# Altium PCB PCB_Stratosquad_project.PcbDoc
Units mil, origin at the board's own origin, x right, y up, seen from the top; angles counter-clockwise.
Board outline 4505 x 4505 mil, 2 copper layers (Top Layer, Bottom Layer); 27 components, 22 nets, 130 pads, 25 vias.
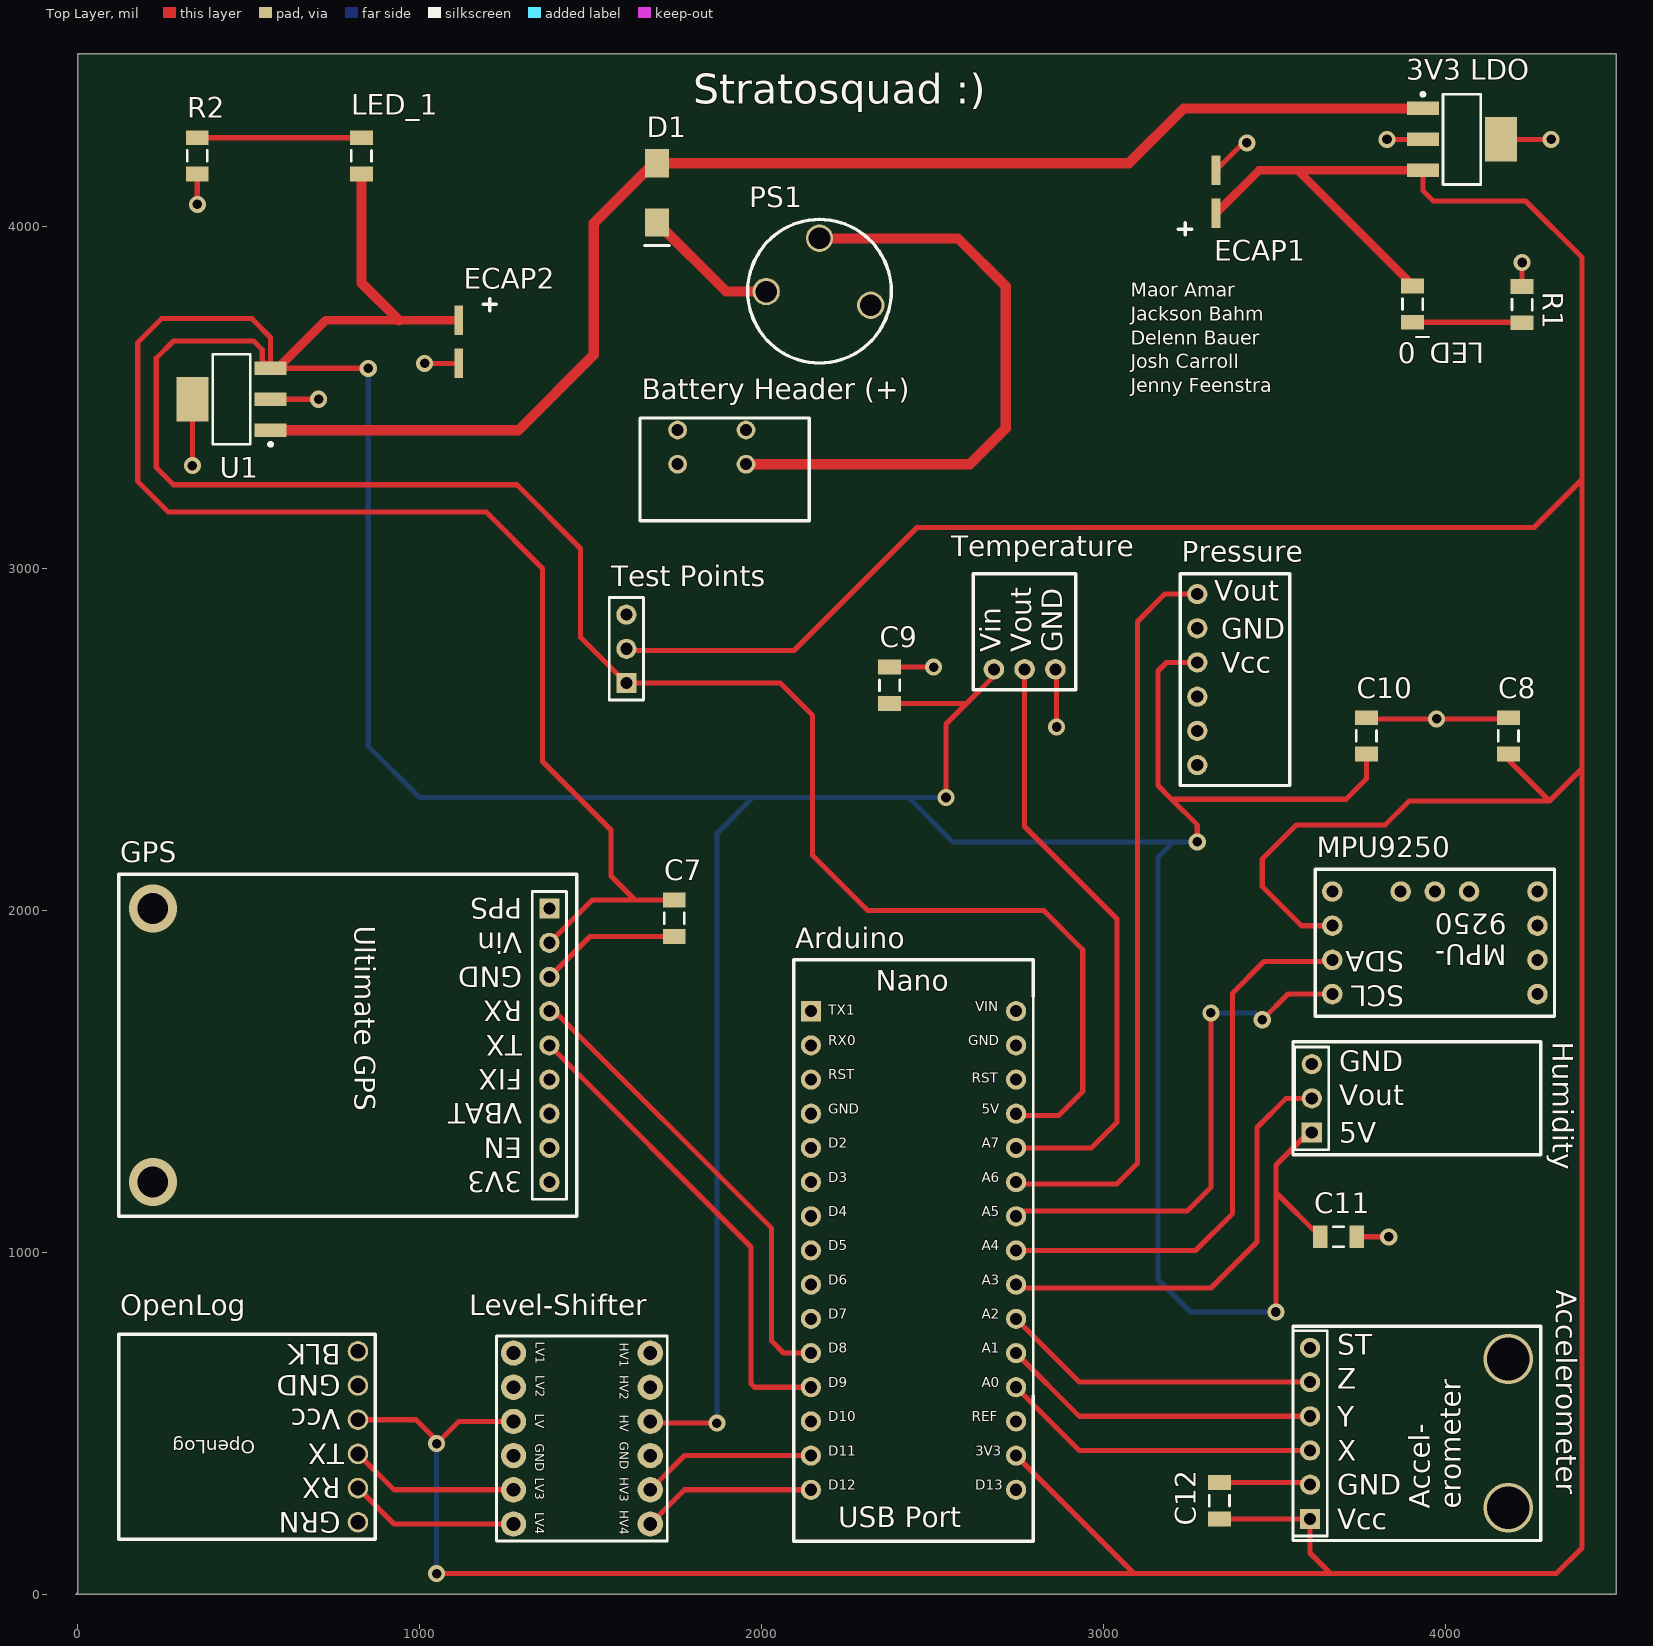
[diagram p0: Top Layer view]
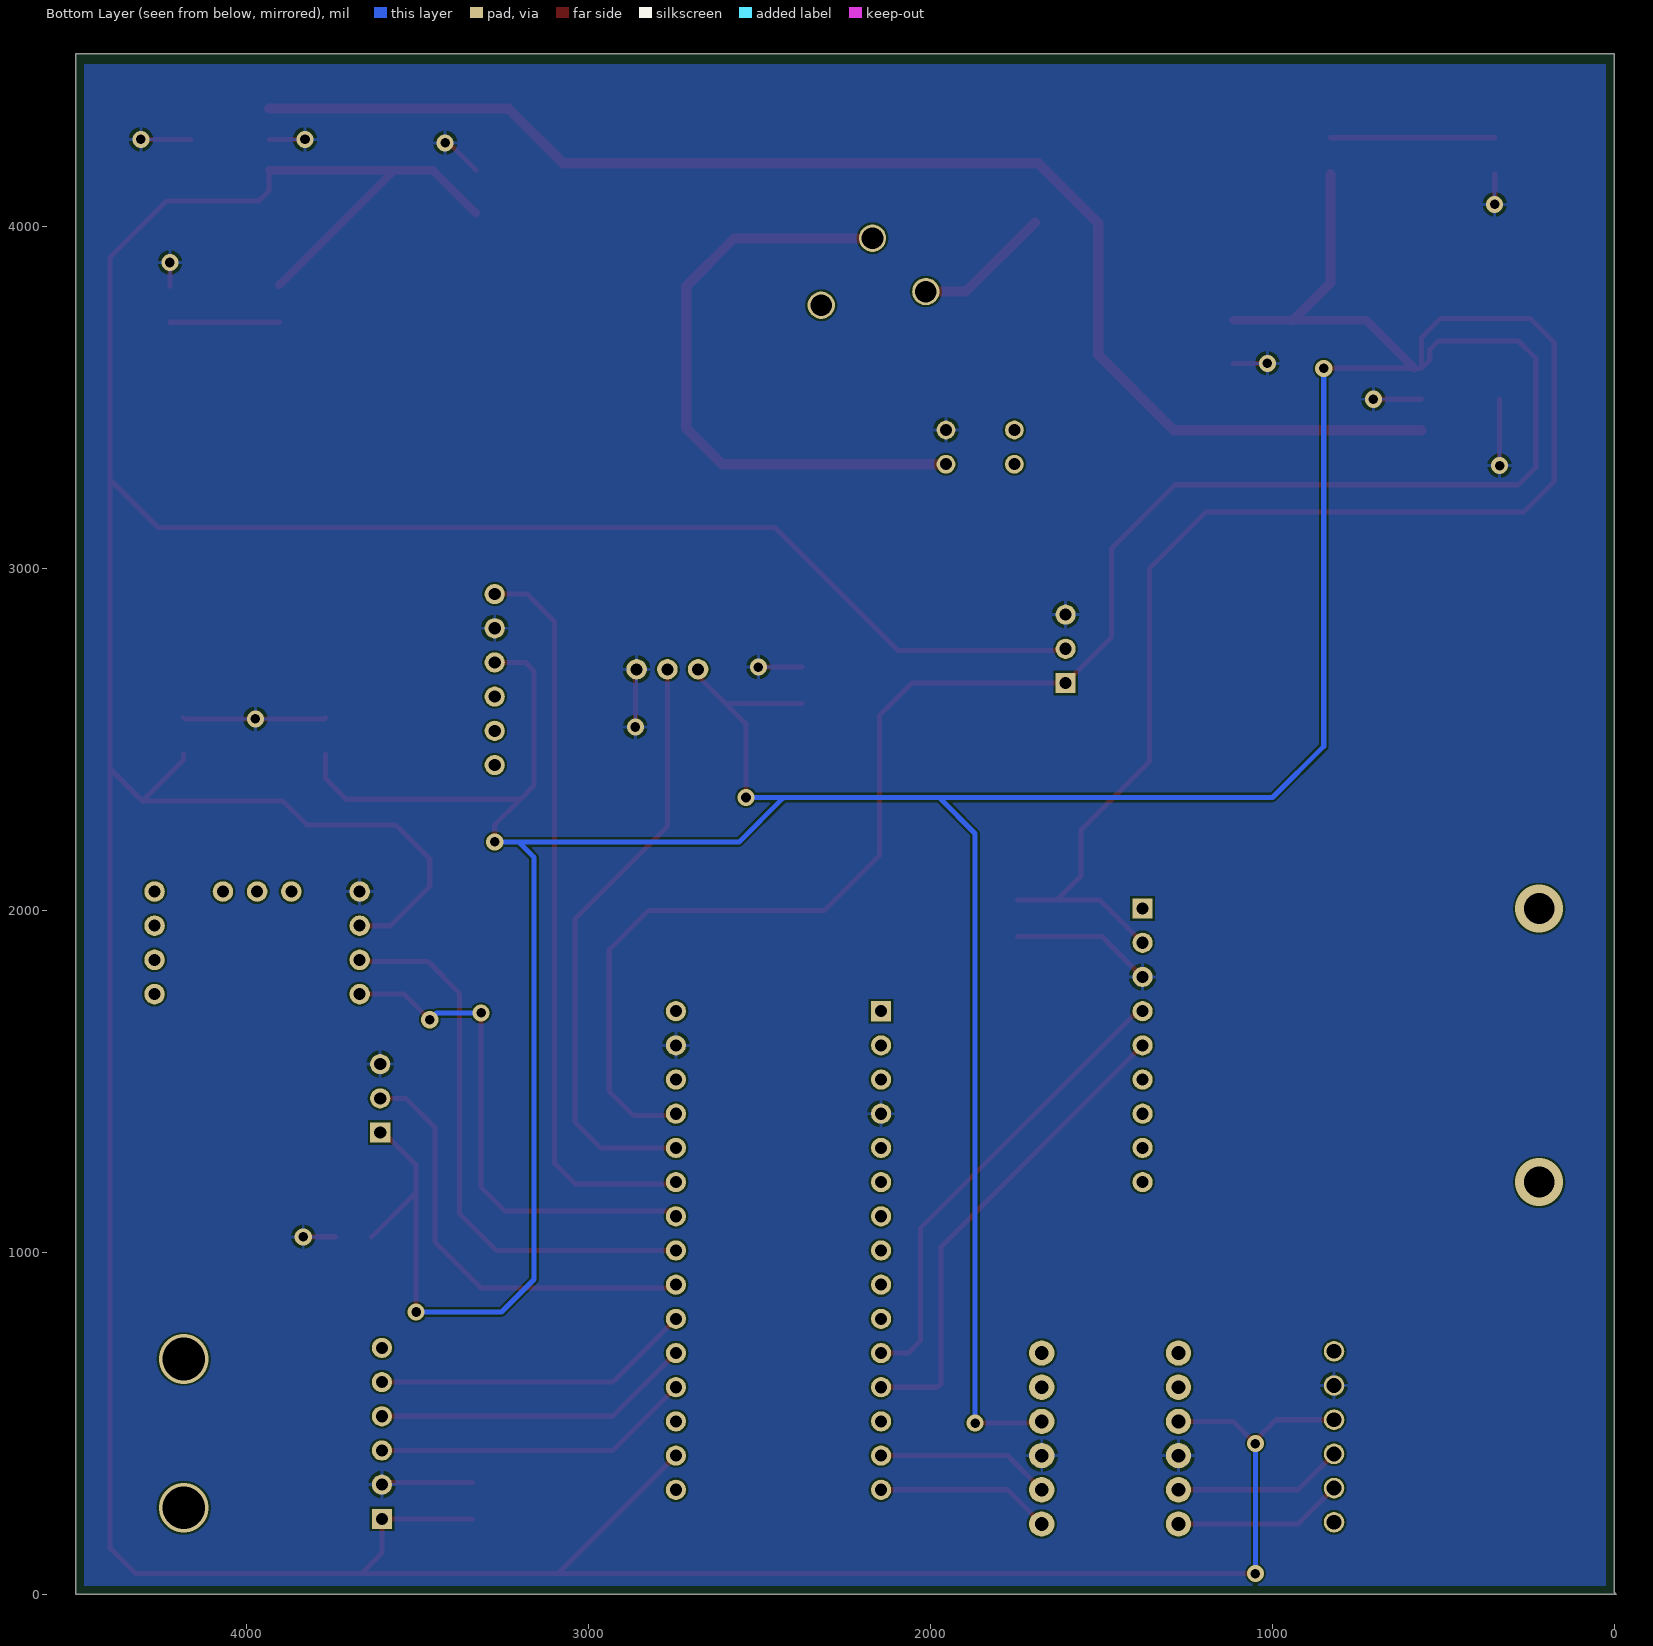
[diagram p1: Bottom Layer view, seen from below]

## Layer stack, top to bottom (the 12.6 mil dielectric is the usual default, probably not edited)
Top Solder: solder mask 0.4, Solder Resist, Dk 3.5
Top Layer: signal copper 1.4
Dielectric 1: dielectric 12.6, FR-4, Dk 4.8
Bottom Layer: signal copper 1.4
Bottom Solder: solder mask 0.4, Solder Resist, Dk 3.5

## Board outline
0,4505 4500,4505 4500,0 -5,0 0,5

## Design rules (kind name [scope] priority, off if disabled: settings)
Clearance [All] p1: gap=6 ignorepadtopadclearanceinfootprint=FALSE
HoleSize [All] p1: absolutevalues=TRUE maxlimit=130 minlimit=13 maxpercent=80.000 minpercent=20.000
MinimumAnnularRing [All] p1: minimumring=7
PolygonConnect [All] p1: connectstyle=Relief reliefconductorwidth=10 reliefentries=4 polygonreliefangle="90 Angle" airgapwidth=10
RoutingVias [All] p1: holewidth=28 width=50 viastyle="Through Hole" minholewidth=28 minwidth=50 maxholewidth=28 maxwidth=50
SilkToSolderMaskClearance [IsPad] p1: minsilkscreentomaskgap=2 clearancetoexposedcopper=TRUE
SolderMaskExpansion [All] p1: expansion=4
Width [All] p1: maxlimit=30 minlimit=6 preferedwidth=15
28 further rules are at their usual default settings.

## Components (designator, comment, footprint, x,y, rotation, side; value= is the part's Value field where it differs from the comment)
"3V3 LDO" "LDO 3V3" SOT223-4N 4049.17,4255 r0 top
Accelerometer "Accelerometer_Breakout" Accelerometer_Breakout 3605,220 r90 top
Arduino "Arduino_Nano" Arduino_Nano 2145,1705 r0 top
"Battery Header (+)" "Battery Header (-)" "Battery Header" 1755,3305 r180 top
C7 "0.1uF" C1206 1745,1976.85 r270 top
C8 "0.1uF" C1206 4185,2510 r90 top
C9 "0.1uF" C1206 2375,2658.15 r90 top
C10 "0.1uF" C1206 3770,2510 r90 top
C11 "0.1uF" C1206 3688.15,1045 r0 top
C12 "0.1uF" C1206 3340,273.15 r90 top
D1 "SMAJ5.0A" SMAJ5.0A 1695,4011.77 r90 top
ECAP1 "Electrolytic Capacitor" "Electrolytic Capacitor" 3330,4102.01 r0 top
ECAP2 "Electrolytic Capacitor" "Electrolytic Capacitor" 1115,3662.99 r180 top
GPS "Adafruit_Ultimate_GPS" Adafruit_Ultimate_GPS 1380,2005 r270 top
Humidity "Humidity_Breakout" Humidity_Breakout 3610,1350 r90 top
LED_0 "Power Status LED" C1206 3905,3773.15 r270 top
LED_1 "Power Status LED" C1206 830,4206.85 r90 top
Level-Shifter "Level Shifter" "Level Shifter" 1275,205 r270 top
MPU9250 "MPU9250" MPU9250 3620,1890 r90 top
OpenLog "Data Logger" OpenLog 510,440 r180 top
Pressure "Pressure Sensor" "Pressure Sensor" 3405,2725 r0 top
PS1 "PinSwitch" SwitchPin 2170,3966 r0 top
R1 "300 kO Res" C1206 4225,3771.85 r90 top
R2 "300 kO Res" C1206 350,4206.85 r270 top
Temperature "TMP36" TMP36 2800,2705 r90 top
"Test Points" "1 = 5V | 2 = 3V3" HDR1X3 1605,2665 r90 top
U1 "LM340" SOT223-4N 450,3495 r180 top

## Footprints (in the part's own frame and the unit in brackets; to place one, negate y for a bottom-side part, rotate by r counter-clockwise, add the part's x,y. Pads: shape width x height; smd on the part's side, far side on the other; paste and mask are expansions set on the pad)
Accelerometer_Breakout [mm]
  rect 1.5x1.5 hole 0.9: 1(0,0)
  round 1.5 hole 0.9: 2(2.54,0) 3(5.08,0) 4(7.62,0) 5(10.16,0) 6(12.7,0)
  silkscreen extent -1.61,-17.14 14.32,1.27, body extent -1.61,-17.09 14.32,1.32, height 2.11
Adafruit_Ultimate_GPS [mm] "Adafruit GPS Breakout Board"
  rect 1.5x1.5 hole 0.9: 1(0,0)
  round 1.5 hole 0.9: 2(2.54,0) 3(5.08,0) 4(7.62,0) 5(10.16,0) 6(12.7,0) 7(15.24,0) 8(17.78,0) 9(20.32,0)
  silkscreen extent -2.54,-32 22.86,2.03, body extent -2.54,-32 22.86,2.03, height 2.11
Arduino_Nano [mm]
  rect 1.5x1.5 hole 0.9: 1(0,0)
  round 1.5 hole 0.9: 2(0,-2.54) 3(0,-5.08) 4(0,-7.62) 5(0,-10.16) 6(0,-12.7) 7(0,-15.24) 8(0,-17.78) 9(0,-20.32) 10(0,-22.86) 11(0,-25.4) 12(0,-27.94) 13(0,-30.48) 14(0,-33.02) 15(0,-35.56) 16(15.24,-35.56) 17(15.24,-33.02) 18(15.24,-30.48) 19(15.24,-27.94) 20(15.24,-25.4) 21(15.24,-22.86) 22(15.24,-20.32) 23(15.24,-17.78) 24(15.24,-15.24) 25(15.24,-12.7) 26(15.24,-10.16) 27(15.24,-7.62) 28(15.24,-5.08) 29(15.24,-2.54) 30(15.24,0)
  silkscreen extent -1.27,-39.37 16.51,3.81, body extent -1.27,-39.37 16.51,3.81, height 2.11
"Battery Header" [mil] "Spring Terminal Battery Header"
  round 55 hole 35: 0(-200,0) 1(-200,-100) 2(0,0) 3(0,-100)
  silkscreen extent -385,-135 110,165, body extent -385,-135 110,165, height 14
C1206 [mm] "Chip Capacitor, Body 3.2x1.6mm, IPC High Density"
  rect 1.1x1.7 smd: 1(-1.35,0) 2(1.35,0)
  silkscreen extent -0.4,-0.75 0.4,0.75, body extent -1.7,-0.9 1.7,0.9, height 1.3
"Electrolytic Capacitor" [mm]
  rect 0.65x2.2 smd: 1(0,-1.6) 2(0,1.6)
  silkscreen extent -2.8,-3.2 -1.8,-2.3
HDR1X3 [mm] "Connector; Header; 3 Position"
  rect 1.5x1.5 hole 0.9: 1(0,0)
  round 1.5 hole 0.9: 2(2.54,0) 3(5.08,0)
  silkscreen extent -1.27,-1.27 6.35,1.27
Humidity_Breakout [mm]
  rect 1.5x1.5 hole 0.9: 1(0,0)
  round 1.5 hole 0.9: 2(2.54,0) 3(5.08,0)
  silkscreen extent -1.65,-17.02 6.73,1.4, body extent -1.65,-17.02 6.73,1.4, height 2.11
"Level Shifter" [mil] "1X06"
  round 74 hole 40: 1(0,0) 2(-100,0) 3(-200,0) 4(-300,0) 5(-400,0) 6(-500,0) 7(0,400) 8(-100,400) 9(-200,400) 10(-300,400) 11(-400,400) 12(-500,400)
  silkscreen extent -550,-50 50,450, body extent -550,-50 50,450, height 500
MPU9250 [mil] "IMU from sparkfun"
  round 60 hole 35: 1(-135,-50) 2(-35,-50) 3(65,-50) 4(165,-50) 5(165,-250) 6(165,-350) 7(165,-450) 8(165,-650) 9(65,-650) 10(-35,-650) 11(-135,-650)
  silkscreen extent -200,-700 230,0, body extent -200,-700 230,0, height 500
OpenLog [mil]
  round 60 hole 43.31: 1(-310,230) 2(-310,130) 3(-310,30) 4(-310,-70) 5(-310,-170) 6(-310,-270)
  silkscreen extent -360,-320 390,280, body extent -360,-320 390,280, height 500
"Pressure Sensor" [mm] "MPX4115A"
  round 1.5 hole 0.9: 1(-3.302,5.08) 2(-3.302,2.54) 3(-3.302,0) 4(-3.302,-2.54) 5(-3.302,-5.08) 6(-3.302,-7.62)
  silkscreen extent -4.57,-9.14 3.56,6.6, body extent -4.57,-9.14 3.56,6.6, height 12.7
SMAJ5.0A [mm]
  rect 2.1x1.8 smd: 1(0,0) 2(4.4,0)
  silkscreen extent -1.7,-0.89 -1.7,0.91
SOT223-4N [mm] "SOT223, 4-Leads, Body 6.5x3.5mm, Pitch 2.3mm, Lead Span 7mm, IPC Medium Density"
  rect 2.4x1 smd: 1(-2.9,2.3) 2(-2.9,0) 3(-2.9,-2.3)
  rect 2.4x3.3 smd: 4(2.9,0)
  silkscreen extent -3.02,-3.35 1.4,3.47, body extent -1.85,-3.35 1.85,3.35, height 1.8
SwitchPin [mil]
  round 80 hole 63: 0(-156,-156) 1(0,0) 2(150,-196)
  silkscreen extent -210,-365 210,55
TMP36 [mil] "TMP36 Temperature Sensor"
  round 60 hole 35: 1(0,120) 2(0,30) 3(0,-60)
  silkscreen extent -60,-120 280,180, body extent -60,-120 280,180, height 500

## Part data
"3V3 LDO": "UA78M05 LDO"
Accelerometer: "ADXL335 3-axis accelerometer"
Arduino: "Arduino Nano board"
"Battery Header (+)": library part "Battery Header"
C7 C8 C9 C10 C11 C12 LED_0 LED_1 R1 R2: library part "Cap Semi", "Capacitor (Semiconductor SIM Model)"
D1: "Circuit Protection Diode"
ECAP1 ECAP2: "Filter Capacitor"
GPS: "UART GPS module from adafruit"
Humidity: "HIH4030 Humidity Sensor Breakout"
Level-Shifter: "Logic Level Shifter from Sparkfun"
MPU9250: "MPU9250 9-axis IMU from Sparkfun"
OpenLog: library part OpenLog
Pressure: "MPX4115A Pressure Sensor"
PS1: "RBF pin for turning on/off payload"
Temperature: "A temperature sensor for ENGR100 TMP36 model"
"Test Points": library part "Header 3", "Header, 3-Pin"
U1: library part "LDO 5V", "LM340 LDO 5V Out"

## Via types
v1: diameter 50, hole 28, Top Layer to Bottom Layer, 21 vias
v2: diameter 145, hole 125, Top Layer to Bottom Layer, 2 vias
v3: diameter 140, hole 90, Top Layer to Bottom Layer, 2 vias

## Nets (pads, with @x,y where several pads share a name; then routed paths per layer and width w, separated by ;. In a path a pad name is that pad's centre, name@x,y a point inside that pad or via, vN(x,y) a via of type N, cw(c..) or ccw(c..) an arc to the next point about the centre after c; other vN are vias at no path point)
3V3: "3V3 LDO.3" "Test Points.2" Accelerometer.1 Arduino.17 C8.1 C12.1 ECAP1.1 LED_0.1 Level-Shifter.4 MPU9250.3 OpenLog.4 | length 15304.9
  Top Layer w15: OpenLog.4 990,510 1050,450 v1(1050,440) 1115,505 Level-Shifter.4 Level-Shifter.4@1270,510 ; v1(1050,60) 3090,60 ; 1605,2765 1610,2760 2095,2760 2455,3120 4260,3120 4400,3260 ; Arduino.17 3090,60 ; C12.1 Accelerometer.1 3605,120 3665,60 ; MPU9250.3 3580,1955 3465,2070 3465,2150 3565,2250 3825,2250 3895,2320 4305,2320 ; LED_0.1 LED_0.1@3905,3829.45 ; 3935,4164.45 3935,4105 3965,4075 4235,4075 4400,3910 4400,3260 ; C8.1 4185,2440 4305,2320 ; 3090,60 3665,60 ; 3665,60 4325,60 4400,135 4400,2415 ; 4305,2320 4400,2415 ; 4400,2415 4400,3260
  Top Layer w25: ECAP1.1 3455.43,4164.45 3570,4164.45 ; LED_0.1@3905,3829.45 3570,4164.45 ; 3935,4164.45 3570,4164.45
  Bottom Layer w15: v1(1050,60) v1(1050,440)
5V: "Test Points.1" Arduino.27 C7.1 C9.1 C10.1 C11.1 ECAP2.1 GPS.2 Humidity.1 LED_1.1 Level-Shifter.10 Pressure.3 Temperature.1 U1.3 | length 20401.2
  Top Layer w15: v1(850,3585) 849.45,3585.55 585.55,3585.55 U1.3 ; GPS.2 1505,2030 1630,2030 ; Level-Shifter.10 1680,500 v1(1870,500) ; C7.1 1630,2030 ; C9.1 2600,2605 ; v1@2530,2340 v1(2540,2330) 2540,2545 2600,2605 ; Temperature.1 2680,2685 2600,2605 ; Arduino.27 2750,1400 2870,1400 2940,1470 2940,1885 2825,2000 2310,2000 2150,2160 2150,2570 2055,2665 1605,2665 1471.25,2798.75 1471.25,3058.75 1285,3245 280,3245 230,3295 230,3615 280,3665 515,3665 540,3640 540,3609.72 U1.3 ; v1(3275,2200) 3275,2250 3200,2325 ; Pressure.3 3185,2725 3160,2700 3160,2365 3200,2325 ; v1(3505,825) 3505,1175 ; Humidity.1 3600,1350 3505,1255 3505,1175 ; C11.1 3505,1175 ; C10.1 3770,2385 3710,2325 3200,2325 ; U1.3 564.17,3675.83 509.17,3730.83 245.83,3730.83 175.83,3660.83 175.83,3254.17 265,3165 1195,3165 1360,3000 1360,2435 1560,2235 1560,2100 1630,2030
  Top Layer w25: U1.3@585.55,3585.55 725.98,3725.98 940,3725.98 ECAP2.1
  Top Layer w30: LED_1.1 830,3835.98 940,3725.98
  Bottom Layer w15: v1(850,3585) 850,2480 1000,2330 1975,2330 ; v1(1870,500) 1870,2225 1975,2330 ; 2432.5,2327.5 2560,2200 3205,2200 ; v1(2540,2330) 1975,2330 ; v1(3275,2200) 3205,2200 ; v1(3505,825) 3255,825 3160,920 3160,2155 3205,2200
"AXDL335 - X": Accelerometer.3 Arduino.19 | length 936.6
  Top Layer w15: Arduino.19 2930,420 Accelerometer.3
"AXDL335 - Y": Accelerometer.4 Arduino.20 | length 936.6
  Top Layer w15: Arduino.20 2930,520 Accelerometer.4
"AXDL335 - Z": Accelerometer.5 Arduino.21 | length 936.6
  Top Layer w15: Arduino.21 2930,620 Accelerometer.5
"Battery - Vin": "3V3 LDO.1" D1.2 U1.1 | length 3986.2
  Top Layer w30: U1.1 1289.45,3404.45 1510,3625 1510,4010 1685,4185 D1.2 3075,4185 3235.55,4345.55 3935,4345.55
GND: "3V3 LDO.2" "3V3 LDO.4" "Battery Header (+).1" "Test Points.3" Accelerometer.2 Arduino.4 Arduino.29 C7.2 C8.2 C9.2 C10.2 C11.2 C12.2 ECAP1.2 ECAP2.2 GPS.3 Humidity.3 Level-Shifter.3 Level-Shifter.9 MPU9250.4 OpenLog.5 Pressure.2 R1.2 R2.2 Temperature.3 U1.2 U1.4 | length 2467.6
  Top Layer w15: v1(335.83,3300.83) U1.4 ; v1(350,4065) R2.2 ; U1.2 v1(705,3495) ; v1(1015,3600) ECAP2.2 ; GPS.3 1498.7,1923.7 C7.2 ; C9.2 v1(2503.7,2711.3) ; Temperature.3 2863.7,2701.3 v1(2863.7,2536.3) ; ECAP1.2 3410,4245 v1(3420,4245) ; C12.2 3598.7,326.3 Accelerometer.2 ; Humidity.3@3605,1555 Humidity.3 ; C11.2 v1(3835,1045) ; C10.2 3773.15,2560 v1(3975,2560) 4181.85,2560 C8.2 ; v1(3830,4255) 3935,4255 ; 4163.35,4255 v1(4310,4255) ; R1.2 v1(4225,3895)
GPS_RX: Arduino.11 GPS.4 | length 1372.5
  Top Layer w15: GPS.4 1395,1705 2030,1070 2030,740 2065,705 Arduino.11
GPS_TX: Arduino.12 GPS.5 | length 1413.5
  Top Layer w15: GPS.5 1970,1015 1970,615 1980,605 Arduino.12
"Humidity - Vout": Arduino.22 Humidity.2 | length 1295.3
  Top Layer w15: Arduino.22 2755,895 3315,895 3450,1030 3450,1365 3535,1450 Humidity.2
"Level-Shift <-> Digital11": Arduino.14 Level-Shifter.8 | length 511.4
  Top Layer w15: Level-Shifter.8 1775,405 Arduino.14
"Level-Shift <-> Digital12": Arduino.15 Level-Shifter.7 | length 511.4
  Top Layer w15: Level-Shifter.7 1775,305 Arduino.15
"MPU9250 - A4": Arduino.23 MPU9250.2 | length 1654.9
  Top Layer w15: Arduino.23 3270,1005 3378.5,1113.5 3378.5,1758.5 3470,1850 3665,1850 MPU9250.2
"MPU9250 - A5": Arduino.24 MPU9250.1 | length 1509.6
  Top Layer w15: Arduino.24 2760,1120 3245,1120 3315,1190 v1(3315,1700) ; v1(3465,1680) 3540,1755 MPU9250.1
  Bottom Layer w15: v1(3315,1700) 3445,1700 v1(3465,1680)
"NetBattery Header (+)_0": "Battery Header (+).0" PS1.1 | length 1821.9
  Top Layer w30: 1955,3305 2610,3305 2715,3410 2715,3825 2575,3965 2171,3965 PS1.1
NetD1_1: D1.1 PS1.0 | length 402.6
  Top Layer w30: D1.1 1896.77,3810 PS1.0
NetLED_0_2: LED_0.2 R1.1 | length 320
  Top Layer w15: LED_0.2 R1.1@4225,3720
NetLED_1_2: LED_1.2 R2.1 | length 480
  Top Layer w15: R2.1 LED_1.2
"OpenLog - Rx1": Level-Shifter.1 OpenLog.2 | length 498.5
  Top Layer w15: OpenLog.2 925,205 Level-Shifter.1
"OpenLog - TxO": Level-Shifter.2 OpenLog.3 | length 498.5
  Top Layer w15: OpenLog.3 925,305 Level-Shifter.2
"Pressure - Vout": Arduino.25 Pressure.1 | length 2175.1
  Top Layer w15: Arduino.25 2750,1200 3040,1200 3100,1260 3100,2845 3180,2925 Pressure.1
"TMP36 - Vout": Arduino.26 Temperature.2 | length 1762.9
  Top Layer w15: Arduino.26 2965,1305 3040,1380 3040,1975 2770,2245 Temperature.2
pads on no net: "Battery Header (+).2" "Battery Header (+).3" Accelerometer.6 Arduino.1 Arduino.2 Arduino.3 Arduino.5 Arduino.6 Arduino.7 Arduino.8 Arduino.9 Arduino.10 Arduino.13 Arduino.16 Arduino.18 Arduino.28 Arduino.30 GPS.1 GPS.6 GPS.7 GPS.8 GPS.9 Level-Shifter.5 Level-Shifter.6 Level-Shifter.11 Level-Shifter.12 MPU9250.5 MPU9250.6 MPU9250.7 MPU9250.8 MPU9250.9 MPU9250.10 MPU9250.11 OpenLog.1 OpenLog.6 Pressure.4 Pressure.5 Pressure.6 PS1.2
copper on no net:
  other v2: 4185,252.5 4185,687.5
  other v3: 220,1205 220,2005

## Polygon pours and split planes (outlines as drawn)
GND on Bottom Layer "Bottom Layer - GND" (solid, pour order 6): 25,4475 4475,4475 4475,25 25,25

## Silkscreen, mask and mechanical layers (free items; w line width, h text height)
Top Overlay:
  text "Stratosquad :)" at 1800,4330 h150
  text "Maor Amar / Jackson Bahm / Delenn Bauer / Josh Carroll / Jenny Feenstra" at 3080,3500.42 h70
